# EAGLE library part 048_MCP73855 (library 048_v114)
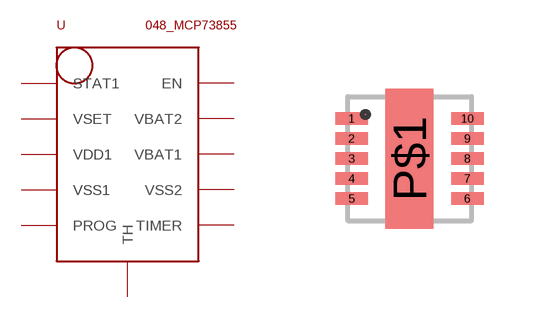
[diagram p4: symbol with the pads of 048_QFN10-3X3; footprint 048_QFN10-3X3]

Designator prefix -

## 048_MCP73855  [048_QFN10-3X3]
1  STAT1
2  VSET
3  VDD1
4  VSS1
5  PROG
6  TIMER
7  VSS2
8  VBAT1
9  VBAT2
10  EN
P$1  TH

## Footprint 048_QFN10-3X3 (pad centres in mm)
smd 0.813 x 0.305: 1 -1.45,1; 2 -1.45,0.5; 3 -1.45,0; 4 -1.45,-0.5; 5 -1.45,-1; 6 1.45,-1; 7 1.45,-0.5; 8 1.45,0; 9 1.45,0.5; 10 1.45,1
smd 1.2 x 3.5: P$1 0,0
